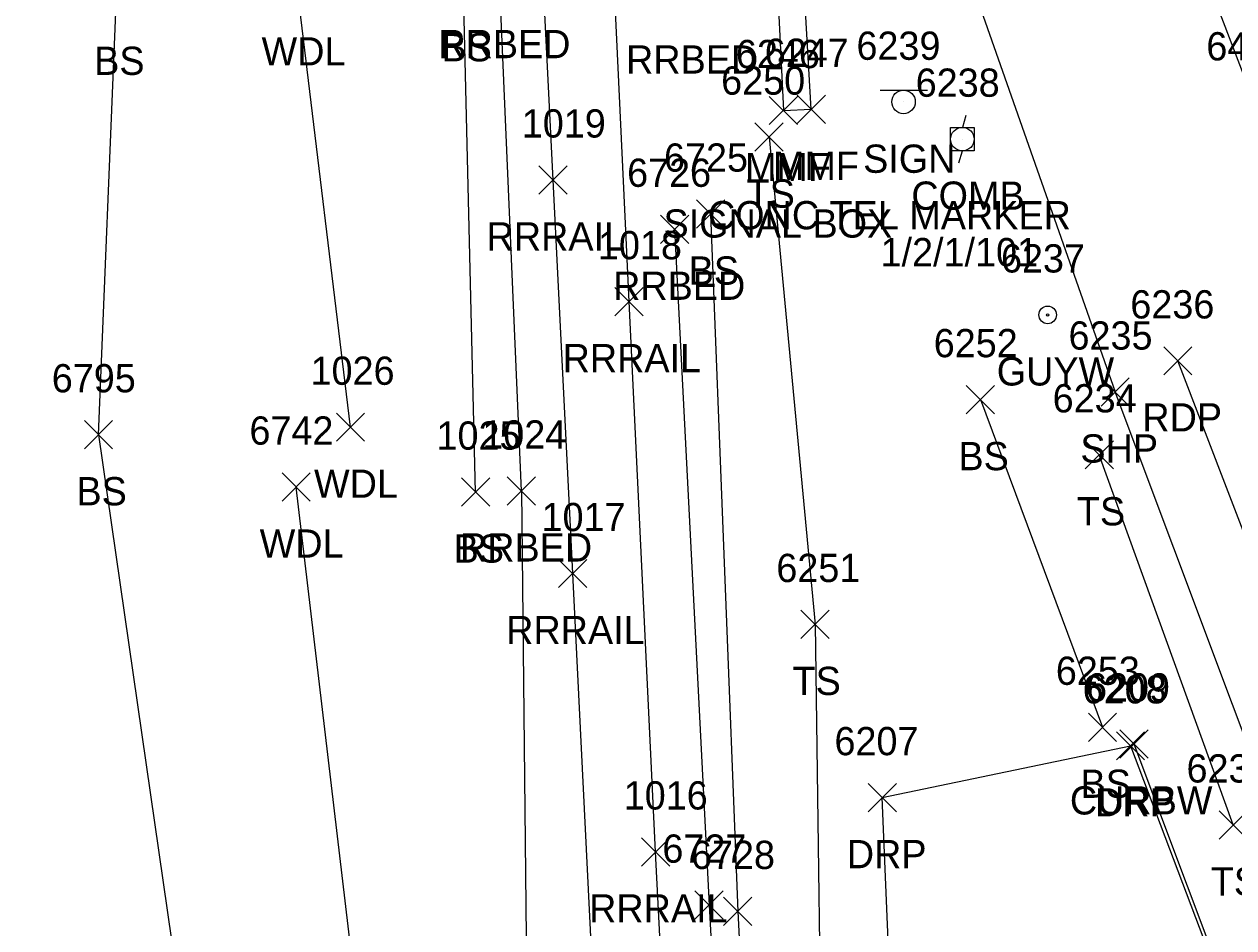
# Model space of a CAD drawing. Extents: x 1769141 to 1770817, y 735471 to 742405.
# Drawn here: x 1770143.6 to 1770229.2, y 740677.5 to 740741.5 of the extents above; entities that cross this region are included whole.
import ezdxf

# ---------------------------------------------------------------- set-up
doc = ezdxf.new("R2010")
doc.units = 0
for name, color, linetype in [('L_A', 7, 'Continuous'), ('L_C', 7, 'Continuous'), ('L_I', 7, 'Continuous'), ('L_TIC', 7, 'Continuous'), ('LAWA', 7, 'Continuous'), ('LDEFAULT', 7, 'Continuous'), ('LELB', 7, 'Continuous'), ('P_A', 7, 'Continuous'), ('P_I', 7, 'Continuous'), ('P_TIC', 7, 'Continuous'), ('PET', 7, 'Continuous'), ('PRC', 7, 'Continuous'), ('PSP', 7, 'Continuous'), ('R_A', 7, 'Continuous'), ('R_I', 7, 'Continuous'), ('R_TIC', 7, 'Continuous'), ('RC', 7, 'Continuous'), ('RDP', 7, 'Continuous'), ('RR', 7, 'Continuous'), ('RRB', 7, 'Continuous'), ('S_A', 7, 'Continuous'), ('S_C', 7, 'Continuous'), ('S_I', 7, 'Continuous'), ('SSGN', 7, 'Continuous'), ('U_A', 7, 'Continuous'), ('U_C', 7, 'Continuous'), ('U_I', 7, 'Continuous'), ('UP', 7, 'Continuous'), ('UPGW', 7, 'Continuous')]:
    doc.layers.add(name, color=color, linetype=linetype)

msp = doc.modelspace()

# ---------------------------------------------------------------- linework, layer by layer
at = {"layer": 'L_TIC'}
for points in [[(1770196.336, 740734.362), (1770198.336, 740736.362)], [(1770198.336, 740734.362), (1770196.336, 740736.362)], [(1770198.316, 740734.452), (1770200.316, 740736.452)], [(1770200.316, 740734.452), (1770198.316, 740736.452)], [(1770195.325, 740732.485), (1770197.325, 740734.485)], [(1770197.325, 740732.485), (1770195.325, 740734.485)], [(1770191.188, 740727.033), (1770193.188, 740729.033)], [(1770193.188, 740727.033), (1770191.188, 740729.033)], [(1770210.295, 740713.894), (1770212.295, 740715.894)], [(1770212.295, 740713.894), (1770210.295, 740715.894)], [(1770165.676, 740711.941), (1770167.676, 740713.941)], [(1770167.676, 740711.941), (1770165.676, 740713.941)], [(1770147.826, 740711.408), (1770149.826, 740713.408)], [(1770149.826, 740711.408), (1770147.826, 740713.408)], [(1770218.717, 740709.986), (1770220.717, 740711.986)], [(1770220.717, 740709.986), (1770218.717, 740711.986)], [(1770161.827, 740707.705), (1770163.827, 740709.705)], [(1770163.827, 740707.705), (1770161.827, 740709.705)], [(1770174.543, 740707.348), (1770176.543, 740709.348)], [(1770176.543, 740707.348), (1770174.543, 740709.348)], [(1770198.579, 740697.976), (1770200.579, 740699.976)], [(1770200.579, 740697.976), (1770198.579, 740699.976)], [(1770218.944, 740690.696), (1770220.944, 740692.696)], [(1770220.944, 740690.696), (1770218.944, 740692.696)], [(1770228.201, 740683.78), (1770230.201, 740685.78)], [(1770230.201, 740683.78), (1770228.201, 740685.78)], [(1770193.101, 740677.657), (1770195.101, 740679.657)], [(1770195.101, 740677.657), (1770193.101, 740679.657)]]:
    msp.add_lwpolyline(points, dxfattribs=at)
at = {"layer": 'LAWA'}
for points in [[(1770166.676, 740712.941), (1770162.961, 740743.553), (1770157.924, 740778.482), (1770151.714, 740790.309), (1770148.066, 740813.544), (1770151.877, 740824.212), (1770145.729, 740849.033), (1770141.17, 740862.727)], [(1770170.455, 740620.932), (1770167.361, 740670.432), (1770162.827, 740708.705)]]:
    msp.add_lwpolyline(points, dxfattribs=at)
at = {"layer": 'LDEFAULT'}
for points in [[(1770197.336, 740735.362), (1770199.316, 740735.452), (1770198.493, 740749.37), (1770196.653, 740749.268)], [(1770196.653, 740749.268), (1770197.336, 740735.362)]]:
    msp.add_lwpolyline(points, dxfattribs=at)
at = {"layer": 'LELB'}
for points in [[(1770175.543, 740708.348), (1770174.677, 740743.844), (1770173.121, 740779.848), (1770172.378, 740797.524), (1770169.979, 740828.468), (1770163.01, 740848.807), (1770152.862, 740876.538)], [(1770148.826, 740712.408), (1770150.082, 740742.883), (1770146.807, 740773.115), (1770137.187, 740805.718), (1770137.504, 740834.463), (1770138.563, 740856.816)], [(1770196.325, 740733.485), (1770199.579, 740698.976), (1770200.143, 740658.947), (1770201.044, 740625.898)], [(1770192.188, 740728.033), (1770194.101, 740678.657), (1770196.518, 740630.705), (1770199.659, 740577.681), (1770202.229, 740519.285)], [(1770211.295, 740714.894), (1770219.944, 740691.696)], [(1770148.826, 740712.408), (1770156.758, 740657.51)], [(1770229.201, 740684.78), (1770219.717, 740710.986)]]:
    msp.add_lwpolyline(points, dxfattribs=at)
at = {"layer": 'P_TIC'}
for points in [[(1770224.275, 740716.638), (1770226.275, 740718.638)], [(1770226.275, 740716.638), (1770224.275, 740718.638)], [(1770219.842, 740714.434), (1770221.842, 740716.434)], [(1770221.842, 740714.434), (1770219.842, 740716.434)]]:
    msp.add_lwpolyline(points, dxfattribs=at)
at = {"layer": 'PET'}
for points in [[(1770207.649, 740753.013), (1770220.842, 740715.434)], [(1770354.076, 740371.381), (1770337.263, 740416.852), (1770319.322, 740465.72), (1770304.605, 740505.641), (1770288.874, 740548.761), (1770274.108, 740588.898), (1770250.942, 740650.858), (1770225.275, 740717.638)]]:
    msp.add_lwpolyline(points, dxfattribs=at)
at = {"layer": 'PRC'}
msp.add_lwpolyline([(1770221.591, 740759.673), (1770230.69, 740735.91)], dxfattribs=at)
at = {"layer": 'PSP'}
msp.add_lwpolyline([(1770346.984, 740368.275), (1770329.75, 740414.987), (1770313.12, 740462.55), (1770298.148, 740502.386), (1770298.12, 740506.759), (1770283.521, 740546.608), (1770275.494, 740567.79), (1770273.862, 740568.65), (1770259.199, 740607.52), (1770260.252, 740609.599), (1770245.76, 740649.038), (1770220.842, 740715.434)], dxfattribs=at)
at = {"layer": 'R_TIC'}
for points in [[(1770180.022, 740729.449), (1770182.022, 740731.449)], [(1770182.022, 740729.449), (1770180.022, 740731.449)], [(1770188.633, 740725.957), (1770190.633, 740727.957)], [(1770190.633, 740725.957), (1770188.633, 740727.957)], [(1770185.409, 740720.831), (1770187.409, 740722.831)], [(1770187.409, 740720.831), (1770185.409, 740722.831)], [(1770177.785, 740707.427), (1770179.785, 740709.427)], [(1770179.785, 740707.427), (1770177.785, 740709.427)], [(1770181.414, 740701.58), (1770183.414, 740703.58)], [(1770183.414, 740701.58), (1770181.414, 740703.58)], [(1770220.922, 740689.38), (1770222.922, 740691.38)], [(1770222.922, 740689.38), (1770220.922, 740691.38)], [(1770221.167, 740689.517), (1770223.167, 740691.517)], [(1770223.167, 740689.517), (1770221.167, 740691.517)], [(1770203.343, 740685.713), (1770205.343, 740687.713)], [(1770205.343, 740685.713), (1770203.343, 740687.713)], [(1770187.287, 740681.87), (1770189.287, 740683.87)], [(1770189.287, 740681.87), (1770187.287, 740683.87)], [(1770191.076, 740678.103), (1770193.076, 740680.103)], [(1770193.076, 740678.103), (1770191.076, 740680.103)]]:
    msp.add_lwpolyline(points, dxfattribs=at)
at = {"layer": 'RC'}
msp.add_lwpolyline([(1770222.167, 740690.517), (1770237.265, 740650.298), (1770253.55, 740607.023), (1770255.095, 740606.238), (1770259.178, 740607.602), (1770260.094, 740609.399), (1770245.65, 740648.982)], dxfattribs=at)
at = {"layer": 'RDP'}
msp.add_lwpolyline([(1770231.873, 740521.702), (1770212.896, 740515.589), (1770209.693, 740561.92), (1770208.231, 740601.592), (1770205.853, 740650.74), (1770204.343, 740686.713), (1770221.922, 740690.38), (1770237.174, 740650.124), (1770253.283, 740606.934), (1770255.089, 740605.917), (1770259.199, 740607.52)], dxfattribs=at)
at = {"layer": 'RR'}
for points in [[(1770197.753, 740390.494), (1770195.855, 740429.491), (1770193.917, 740468.481), (1770191.987, 740507.454), (1770190.016, 740546.417), (1770188.175, 740585.45), (1770186.345, 740624.52), (1770184.351, 740663.534), (1770182.414, 740702.58), (1770181.022, 740730.449), (1770179.246, 740766.268), (1770177.157, 740810.299), (1770173.744, 740877.111), (1770171.322, 740927.707), (1770169.445, 740967.981), (1770167.613, 741006.359), (1770166.537, 741027.4), (1770165.653, 741046.208), (1770163.837, 741084.651), (1770161.662, 741123.764), (1770160.41, 741153.194), (1770158.416, 741192.158), (1770156.873, 741228.018)], [(1770203.658, 740370.746), (1770201.768, 740409.672), (1770199.783, 740448.72), (1770197.896, 740487.783), (1770195.957, 740526.733), (1770194.091, 740565.766), (1770192.139, 740604.842), (1770190.284, 740643.849), (1770188.287, 740682.87), (1770186.409, 740721.831), (1770184.146, 740769.997), (1770182.623, 740801.289), (1770179.628, 740862.115), (1770176.856, 740918.905), (1770174.1, 740971.708), (1770172.224, 741013.506), (1770171.361, 741030.469), (1770170.329, 741051.221), (1770168.957, 741081.093), (1770166.986, 741119.982), (1770165.661, 741147.286), (1770164.69, 741163.317), (1770164.281, 741173.164), (1770162.436, 741212.293)]]:
    msp.add_lwpolyline(points, dxfattribs=at)
at = {"layer": 'RRB'}
for points in [[(1770178.785, 740708.427), (1770177.251, 740744.065), (1770175.209, 740779.841), (1770173.847, 740798.555), (1770169.979, 740828.468)], [(1770189.633, 740726.957), (1770192.076, 740679.103), (1770194.722, 740629.942), (1770197.159, 740578.368), (1770199.016, 740518.432)], [(1770178.785, 740708.427), (1770179.163, 740672.302)]]:
    msp.add_lwpolyline(points, dxfattribs=at)
at = {"layer": 'SSGN'}
for p, q in [((1770204.204, 740736.805), (1770207.537, 740736.805)), ((1770205.85, 740735.972), (1770205.85, 740735.972))]:
    msp.add_line(p, q, dxfattribs=at)
msp.add_circle((1770205.85, 740735.972), 0.833, dxfattribs=at)
at = {"layer": 'UP'}
for p, q in [((1770210.267, 740735.002), (1770210.017, 740734.169)), ((1770209.183, 740732.502), (1770209.183, 740734.169)), ((1770209.183, 740734.169), (1770210.85, 740734.169)), ((1770210.85, 740734.169), (1770210.85, 740732.502)), ((1770210.85, 740732.502), (1770209.183, 740732.502)), ((1770209.767, 740731.669), (1770210.017, 740732.502)), ((1770210.017, 740733.335), (1770210.017, 740733.335))]:
    msp.add_line(p, q, dxfattribs=at)
msp.add_circle((1770210.017, 740733.335), 0.833, dxfattribs=at)
at = {"layer": 'UPGW'}
for radius in [0.625, 0.0833]:
    msp.add_circle((1770216.057, 740720.892), radius, dxfattribs=at)

# ---------------------------------------------------------------- texts
at = {"layer": 'L_A'}
for s, p in [('WDL', (1770160.378, 740738.553)), ('BS', (1770173.118, 740738.844)), ('BS', (1770148.523, 740737.883)), ('MMF', (1770194.619, 740730.362)), ('MMF', (1770196.6, 740730.452)), ('TS', (1770194.734, 740728.485)), ('BS', (1770190.629, 740723.033)), ('BS', (1770209.736, 740709.894)), ('BS', (1770147.267, 740707.408)), ('WDL', (1770164.093, 740707.941)), ('TS', (1770218.127, 740705.986)), ('WDL', (1770160.244, 740703.705)), ('BS', (1770173.984, 740703.348)), ('TS', (1770197.989, 740693.976)), ('BS', (1770218.385, 740686.696)), ('TS', (1770227.61, 740679.78))]:
    msp.add_text(s, height=2, dxfattribs=at).set_placement(p)
at = {"layer": 'L_C'}
msp.add_text('SIGNAL BOX', height=2, dxfattribs=at).set_placement((1770188.848, 740726.362))
at = {"layer": 'L_I'}
for s, p in [('6246', (1770193.974, 740738.362)), ('6247', (1770196.009, 740738.452)), ('6250', (1770192.931, 740736.485)), ('6725', (1770188.881, 740731.033)), ('6252', (1770207.988, 740717.894)), ('1026', (1770163.849, 740715.941)), ('6795', (1770145.519, 740715.408)), ('6234', (1770216.41, 740713.986)), ('6742', (1770159.52, 740711.705)), ('1025', (1770172.771, 740711.348)), ('6251', (1770196.839, 740701.976)), ('6253', (1770216.637, 740694.696)), ('6233', (1770225.894, 740687.78)), ('6728', (1770190.794, 740681.657))]:
    msp.add_text(s, height=2, dxfattribs=at).set_placement(p)
at = {"layer": 'P_A'}
for s, p in [('RDP', (1770222.763, 740712.638)), ('SHP', (1770218.377, 740710.434))]:
    msp.add_text(s, height=2, dxfattribs=at).set_placement(p)
at = {"layer": 'P_I'}
for s, p in [('6450', (1770227.296, 740738.91)), ('6236', (1770221.913, 740720.638)), ('6235', (1770217.535, 740718.434))]:
    msp.add_text(s, height=2, dxfattribs=at).set_placement(p)
at = {"layer": 'R_A'}
for s, p in [('RRBED', (1770172.897, 740739.065)), ('RRBED', (1770186.195, 740737.976)), ('RRRAIL', (1770176.314, 740725.449)), ('RRBED', (1770185.279, 740721.957)), ('RRRAIL', (1770181.7, 740716.831)), ('RRBED', (1770174.43, 740703.427)), ('RRRAIL', (1770177.705, 740697.58)), ('CURBW', (1770217.631, 740685.517)), ('DRP', (1770219.411, 740685.38)), ('DRP', (1770201.831, 740681.713)), ('RRRAIL', (1770183.579, 740677.87))]:
    msp.add_text(s, height=2, dxfattribs=at).set_placement(p)
at = {"layer": 'R_I'}
for s, p in [('1019', (1770178.81, 740733.449)), ('6726', (1770186.271, 740729.957)), ('1018', (1770184.204, 740724.831)), ('1024', (1770176.013, 740711.427)), ('1017', (1770180.209, 740705.58)), ('6208', (1770218.537, 740693.38)), ('6209', (1770218.773, 740693.517)), ('6207', (1770200.957, 740689.713)), ('1016', (1770186.028, 740685.87)), ('6727', (1770188.769, 740682.103))]:
    msp.add_text(s, height=2, dxfattribs=at).set_placement(p)
at = {"layer": 'S_A'}
msp.add_text('SIGN', height=2, dxfattribs=at).set_placement((1770202.988, 740730.952))
at = {"layer": 'S_C'}
msp.add_text('CONC TEL MARKER', height=2, dxfattribs=at).set_placement((1770191.996, 740726.952))
at = {"layer": 'S_I'}
msp.add_text('6239', height=2, dxfattribs=at).set_placement((1770202.516, 740738.952))
at = {"layer": 'U_A'}
for s, p in [('COMB', (1770206.403, 740728.335)), ('GUYW', (1770212.451, 740715.892))]:
    msp.add_text(s, height=2, dxfattribs=at).set_placement(p)
at = {"layer": 'U_C'}
msp.add_text('1/2/1/101', height=2, dxfattribs=at).set_placement((1770204.222, 740724.335))
at = {"layer": 'U_I'}
for s, p in [('6238', (1770206.71, 740736.335)), ('6237', (1770212.75, 740723.892))]:
    msp.add_text(s, height=2, dxfattribs=at).set_placement(p)

doc.saveas('drawing.dxf')
